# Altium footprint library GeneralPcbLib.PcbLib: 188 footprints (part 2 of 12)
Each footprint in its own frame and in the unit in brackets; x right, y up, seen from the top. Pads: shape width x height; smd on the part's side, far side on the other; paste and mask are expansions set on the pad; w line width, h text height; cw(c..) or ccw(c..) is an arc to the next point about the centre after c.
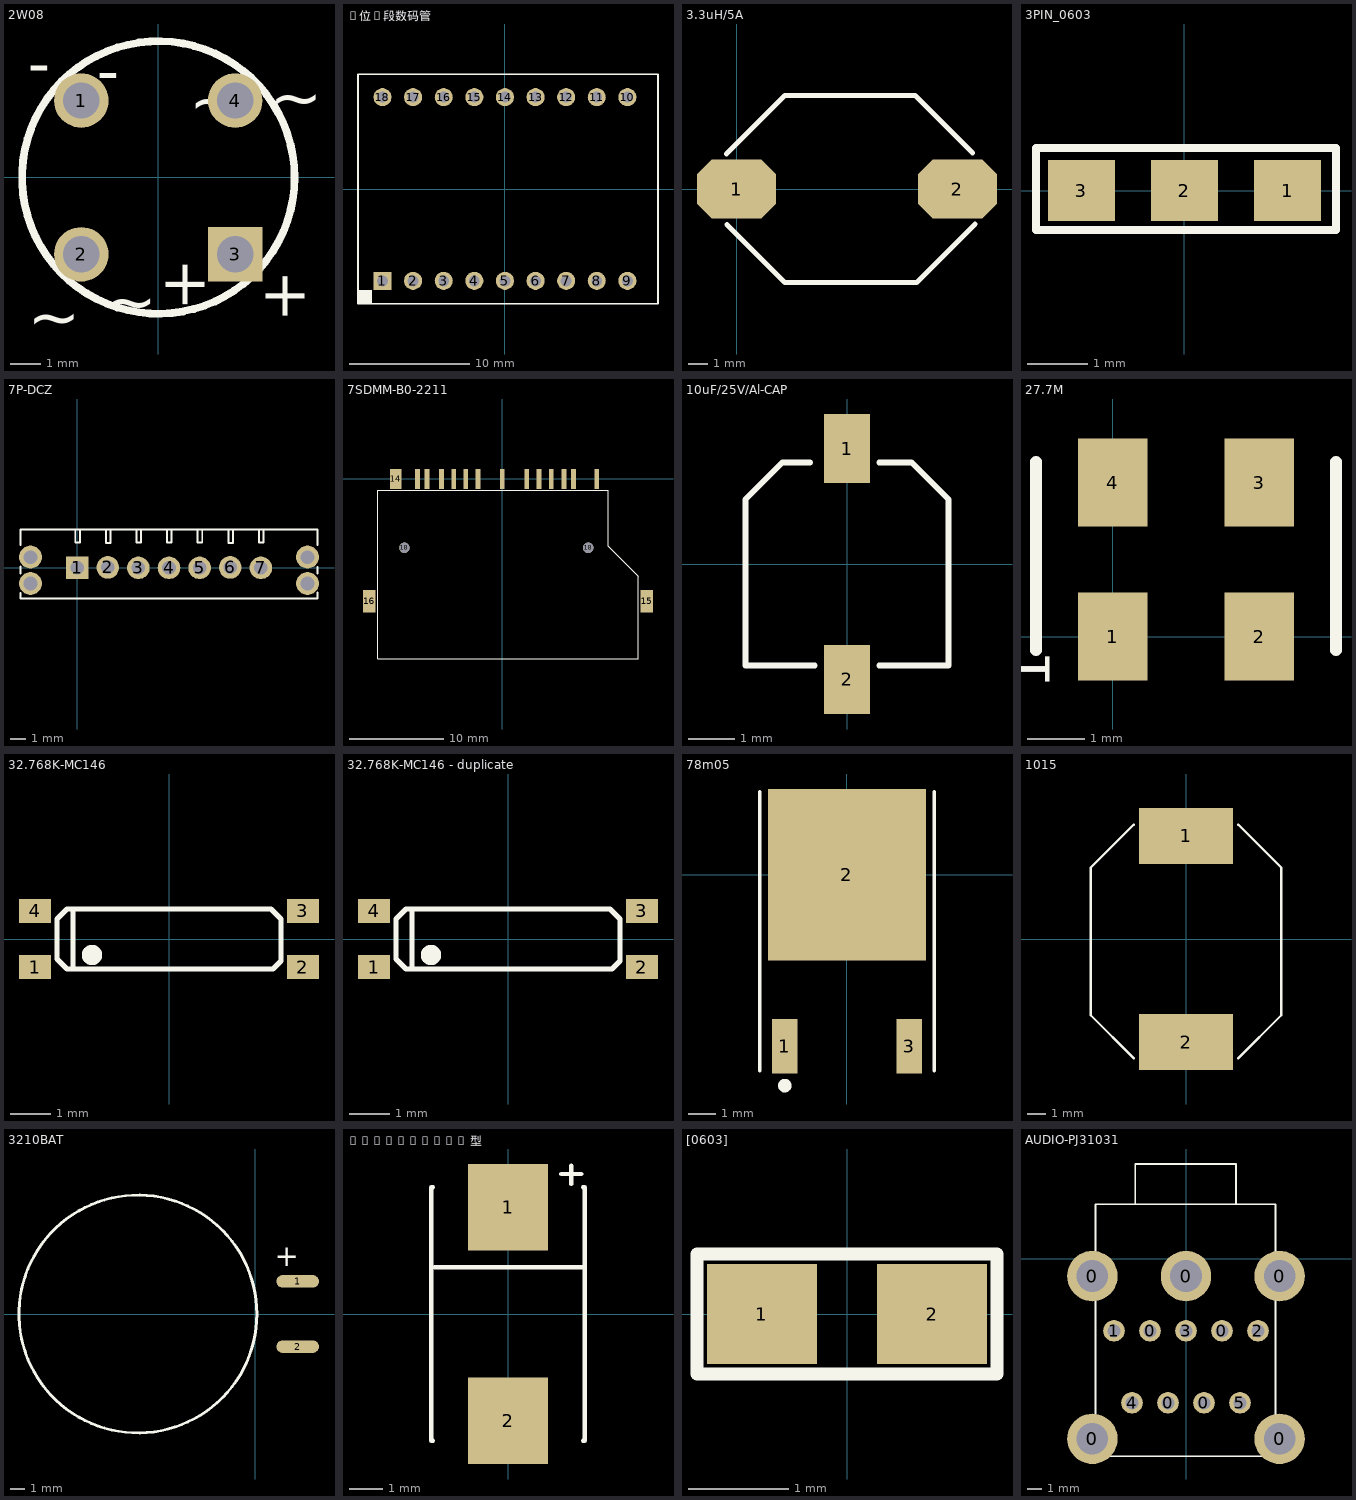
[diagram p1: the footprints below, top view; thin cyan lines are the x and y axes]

## 2W08 [mm] "整流桥"
pads (4):
  round 1.8 hole 1.2: 1(-2.54,2.54) 2(-2.54,-2.54) 4(2.54,2.54)
  rect 1.8x1.8 hole 1.2: 3(2.54,-2.54)
Top Overlay:
  circle w0.254: c0,0 r4.5
  text "+" at 3.556,-3.048 h1.52
  text "+" at 0.254,-2.667 h1.52
  text "-" at -4.318,3.048 h1.52
  text "-" at -2.032,2.794 h1.52
  text "~" at -1.778,-4.826 h1.52
  text "~" at 1.016,1.778 h1.52
  text "~" at 3.683,1.905 h1.52
  text "~" at -4.318,-5.334 h1.52

## 2位8段数码管 [mm]
pads (18):
  rect 1.5x1.5 hole 0.9: 1(-10.16,-7.62)
  round 1.5 hole 0.9: 2(-7.62,-7.62) 3(-5.08,-7.62) 4(-2.54,-7.62) 5(0,-7.62) 6(2.54,-7.62) 7(5.08,-7.62) 8(7.62,-7.62) 9(10.16,-7.62) 10(10.16,7.62) 11(7.62,7.62) 12(5.08,7.62) 13(2.54,7.62) 14(0,7.62) 15(-2.54,7.62) 16(-5.08,7.62) 17(-7.62,7.62) 18(-10.16,7.62)
Top Overlay:
  rectangle: -12.192,-9.525 -11.049,-8.382
  lines w0.127: -12.192,-9.525 12.7,-9.525 12.7,9.525 -12.192,9.525 -12.192,-9.525

## 3.3uH/5A [mm]
pads (2):
  oct 4x3 smd: 1(0,0) 2(11.176,0)
Top Overlay:
  lines w0.254: -0.508,1.778 2.442,4.728 9.034,4.728 ; -0.488,-1.798 2.442,-4.728 9.115,-4.728 9.167,-4.676 12.065,-1.778 ; 9.034,4.728 11.943,1.818 9.034,4.728

## 3PIN_0603 [mm]
pads (3):
  rect 1.1x1 smd: 1(1.7,0) 2(0,0) 3(-1.7,0)
Top Overlay:
  lines w0.127: -2.45,-0.65 2.5,-0.65 2.5,0.7 -2.45,0.7 -2.45,-0.65

## 7P-DCZ [mm] "7P电池座"
height 0.5
pads (11):
  rect 1.5x1.5 hole 0.9: 1(0,0)
  round 1.5 hole 0.9: 2(2.032,0.025) 3(4.064,0) 4(6.096,0) 5(8.128,0) 6(10.16,0.025) 7(12.192,0)
  round 1.524 hole 0.9: ""(-3.099,-1.041) ""(-3.099,0.711) ""(15.291,-1.041) ""(15.291,0.711)
Top Overlay:
  lines w0.127: -3.754,-1.676 -3.754,-2.032 15.946,-2.032 15.946,-1.626 ; -3.754,-0.381 -3.754,0.079 ; -3.754,1.524 -3.754,2.54 15.946,2.54 15.946,1.524 ; -0.127,2.489 -0.127,1.676 0.178,1.676 0.178,2.489 ; 1.905,2.489 1.905,1.651 2.21,1.651 2.21,2.489 ; 3.937,2.489 3.937,1.676 4.242,1.676 4.242,2.489 ; 5.969,2.489 5.969,1.676 6.274,1.676 6.274,2.489 ; 8.001,2.489 8.001,1.676 8.306,1.676 8.306,2.489 ; 10.033,2.489 10.033,1.651 10.338,1.651 10.338,2.489 ; 12.065,2.489 12.065,1.676 12.37,1.676 12.37,2.489 ; 15.946,-0.381 15.946,0.051

## 7SDMM-B0-2211 [mm] "SDcard"
pads (18):
  rect 0.5x2.1 smd: 1(7.58,0) 2(5.2,0) 3(2.6,0) 4(0,0) 5(-2.6,0) 6(-5.2,0) 7(-8.05,0) 8(-9.05,0) 9(10.08,0) 10(6.58,0) 11(3.9,0) 12(-3.9,0) 13(-6.5,0)
  rect 1.2x2.1 smd: 14(-11.38,0)
  rect 1.3x2.4 smd: 15(15.4,-13.05) 16(-14.2,-13.05)
  round 1.1 hole 1.1: 18(-10.45,-7.35) 18(9.15,-7.35)
Top Overlay:
  lines w0.127: -13.3,-19.2 14.5,-19.2 14.5,-10.4 11.3,-7.2 11.3,-1.2 -13.3,-1.2 -13.3,-19.2

## 10uF/25V/Al-CAP [mm] "10uF/25V/Al-CAP"
height 5
pads (2):
  rect 1x1.5 smd: 1(0,2.5) 2(0,-2.5)
Top Overlay:
  lines w0.127: -0.8,2.2 -1.4,2.2 -2.2,1.4 -2.2,-2.2 -0.7,-2.2 ; 0.7,-2.2 2.2,-2.2 2.2,1.4 1.4,2.2 0.7,2.2

## 27.7M [mil]
height 30
pads (4):
  rect 47.24x60 smd: 1(0,0) 2(100,0) 3(100,105) 4(0,105)
Top Overlay:
  lines w8: -52.36,-9.3 -52.36,119.28 ; 152.36,-9.3 152.36,119.28
  text "1" at -43,-36.01 h30

## 32.768K-MC146 [mm] "XTAL-32.768K"
pads (4):
  rect 0.8x0.6 smd: 1(-3.35,-0.7) 2(3.35,-0.7) 3(3.35,0.7) 4(-3.35,0.7)
Top Overlay:
  circle w0.254: c-1.927,-0.4 r0.127
  lines w0.127: -2.4,-0.75 -2.4,0.75 ; -2.8,-0.5 -2.8,0.5 -2.55,0.75 2.55,0.75 2.8,0.5 2.8,-0.55 2.6,-0.75 -2.55,-0.75 -2.8,-0.5

## 32.768K-MC146 - duplicate [mm] "XTAL-32.768K"
pads (4):
  rect 0.8x0.6 smd: 1(-3.35,-0.7) 2(3.35,-0.7) 3(3.35,0.7) 4(-3.35,0.7)
Top Overlay:
  circle w0.254: c-1.927,-0.4 r0.127
  lines w0.127: -2.4,-0.75 -2.4,0.75 ; -2.8,-0.5 -2.8,0.5 -2.55,0.75 2.55,0.75 2.8,0.5 2.8,-0.55 2.6,-0.75 -2.55,-0.75 -2.8,-0.5

## 78m05 [mm] "1-IN 2-GND 3-OUT"
height 2
pads (3):
  rect 0.95x2 smd: 1(-2.285,-6.3) 3(2.285,-6.3)
  rect 5.8x6.3 smd: 2(0,0)
Top Overlay:
  circle w0.25: c-2.285,-7.75 r0.125
  lines w0.127: -3.2,-7.2 -3.2,3.05 ; 3.2,-7.2 3.2,3.05

## 1015 [mm] "电感 10*15"
pads (2):
  rect 5x3 smd: 1(0,5.5) 2(0,-5.5)
Top Overlay:
  lines w0.127: -2.794,-6.35 -5.08,-4.064 -5.08,3.81 -2.794,6.096 ; 2.794,-6.35 5.08,-4.064 5.08,3.81 2.794,6.096

## 3210BAT [mil]
pads (2):
  oval 120x35 smd: 1(120,92) 2(120,-92)
Top Overlay:
  circle w8: c-330,0 r335
  text "+" at 55,135 h60

## 7473-SMC-C 型 [mm]
height 2.032
pads (2):
  rect 2.4x2.6 smd: 1(0,3.2) 2(0,-3.2)
Top Overlay:
  lines w0.127: -2.25,-3.8 -2.3,-3.8 -2.3,3.8 -2.25,3.8 ; -2.2,1.4 2.3,1.4 ; 1.6,4.2 2.2,4.2 ; 1.9,3.9 1.9,4.45 ; 2.25,-3.8 2.3,-3.8 2.3,3.8 2.25,3.8

## [0603] [mm]
pads (2):
  rect 1.1x1 smd: 1(-0.85,0) 2(0.85,0)
Top Overlay:
  lines w0.127: -1.5,-0.6 -1.5,0.6 1.5,0.6 1.5,-0.6 -1.5,-0.6

## AUDIO-PJ31031 [mm] "PJ31031双层音频座"
pads (14):
  round 3.5 hole 2.2: 0(-6.5,-12.5) 0(-6.5,-1.2) 0(0,-1.2) 0(6.5,-12.5) 0(6.5,-1.2)
  round 1.5 hole 0.9: 0(-2.5,-5) 0(-1.25,-10) 0(1.25,-10) 0(2.5,-5) 1(-5,-5) 2(5,-5) 3(0,-5) 4(-3.75,-10) 5(3.75,-10)
Top Overlay:
  lines w0.127: -3.527,6.584 3.473,6.584 ; -3.527,6.584 -3.527,3.784 -3.527,6.584 ; 3.473,6.584 3.473,3.784 3.473,6.584 ; -6.277,-13.716 6.223,-13.716 6.223,3.784 -6.277,3.784 -6.277,-13.716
